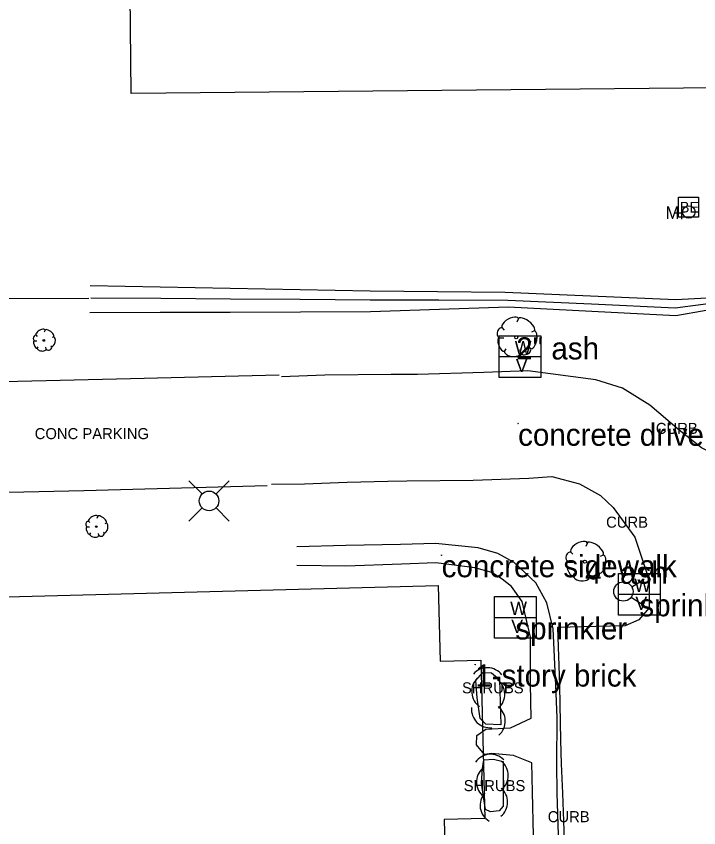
# Model space of a CAD drawing. Extents: x 1802180 to 1804859, y 572524 to 575172.
# Drawn here: x 1803278.7 to 1803432.9, y 574750.8 to 574934.3 of the extents above; entities that cross this region are included whole.
import ezdxf

# ---------------------------------------------------------------- set-up
doc = ezdxf.new("R2010")
doc.units = 0
for name, color, linetype in [('S_BUILDING', 7, 'Continuous'), ('S_CURB_ANNOT', 7, 'Continuous'), ('S_DITCHLINE', 7, 'Continuous'), ('S_ELECTRIC_UTILITIES', 7, 'Continuous'), ('S_MANHOLE', 7, 'Continuous'), ('S_MSC_PT_SYM', 7, 'Continuous'), ('S_PARKING', 7, 'Continuous'), ('S_PARKING_ANNOT', 7, 'Continuous'), ('S_SIDEWALK', 7, 'Continuous'), ('S_STREAM', 7, 'Continuous'), ('S_SURVEY_TEXT_ANNOT', 7, 'Continuous'), ('S_TREE', 7, 'Continuous'), ('S_TREE_ANNOT', 7, 'Continuous'), ('S_UTILITY_POLE', 7, 'Continuous'), ('S_WATER_UTILITIES', 7, 'Continuous'), ('S_WATER_UTILITIES_ANNOT', 7, 'Continuous')]:
    doc.layers.add(name, color=color, linetype=linetype)

msp = doc.modelspace()

# ---------------------------------------------------------------- linework, layer by layer
at = {"layer": 'S_BUILDING'}
for points in [[(1803304.17, 574961.62), (1803436.84, 574962.91), (1803437.28, 574918.07), (1803304.61, 574916.78), (1803304.17, 574961.62)], [(1803186.38, 574730.05), (1803184.53, 574800.55), (1803210.57, 574801.23), (1803210.41, 574807.19), (1803267.74, 574808.69), (1803267.89, 574802.81), (1803374.03, 574805.59), (1803374.48, 574788.48), (1803383.62, 574788.72), (1803384.55, 574752.9), (1803375.35, 574752.66), (1803375.81, 574735.01)]]:
    msp.add_lwpolyline(points, dxfattribs=at)
at = {"layer": 'S_DITCHLINE'}
for points in [[(1803485.39, 574874.75), (1803480.16, 574876.27), (1803462.03, 574877.4), (1803457.78, 574872.83), (1803450.14, 574869.58), (1803434.82, 574870.5), (1803427.71, 574870.12), (1803408.43, 574870.95), (1803389.15, 574871.78), (1803373.89, 574871.95), (1803358.64, 574872.13), (1803342.82, 574872.42), (1803327, 574872.71), (1803311.19, 574873), (1803295.37, 574873.28)], [(1803479.32, 574875.32), (1803464.43, 574874.94), (1803459.71, 574871.25), (1803450.42, 574867.83), (1803435, 574869.25), (1803427.58, 574868.29), (1803408.67, 574869.16), (1803389.76, 574870.03), (1803374.19, 574870.06), (1803358.62, 574870.09), (1803342.85, 574870.2), (1803327.08, 574870.31), (1803311.3, 574870.42), (1803295.53, 574870.53)], [(1803485.66, 574873.78), (1803479.11, 574874.06), (1803465.36, 574872.76), (1803458.52, 574867.76), (1803450.45, 574866.42), (1803434.55, 574867.77), (1803427.69, 574866.53), (1803408.76, 574867.52), (1803389.83, 574868.51), (1803374.28, 574867.97), (1803358.73, 574867.43), (1803342.87, 574867.37), (1803327.01, 574867.31), (1803311.15, 574867.26), (1803295.29, 574867.2)]]:
    msp.add_lwpolyline(points, dxfattribs=at)
at = {"layer": 'S_ELECTRIC_UTILITIES'}
msp.add_lwpolyline([(1803428.33, 574888.83), (1803428.33, 574893.33), (1803432.83, 574893.33), (1803432.83, 574888.83)], close=True, dxfattribs=at)
at = {"layer": 'S_MANHOLE'}
for p, q in [((1803429.07, 574888.39), (1803429.07, 574891.23)), ((1803427.49, 574889.8), (1803429.07, 574889.8))]:
    msp.add_line(p, q, dxfattribs=at)
msp.add_circle((1803430.65, 574890.01), 1.42, dxfattribs=at)
at = {"layer": 'S_MSC_PT_SYM'}
for points in [[(1803392.07, 574842.15), (1803392.07, 574842.2), (1803392.07, 574842.15), (1803392.02, 574842.15), (1803392.07, 574842.15), (1803392.07, 574842.1), (1803392.07, 574842.15), (1803392.12, 574842.15)], [(1803374.8, 574812.43), (1803374.8, 574812.48), (1803374.8, 574812.43), (1803374.75, 574812.43), (1803374.8, 574812.43), (1803374.8, 574812.38), (1803374.8, 574812.43), (1803374.85, 574812.43)], [(1803382.4, 574787.71), (1803382.4, 574787.76), (1803382.4, 574787.71), (1803382.35, 574787.71), (1803382.4, 574787.71), (1803382.4, 574787.66), (1803382.4, 574787.71), (1803382.45, 574787.71)]]:
    msp.add_lwpolyline(points, dxfattribs=at)
at = {"layer": 'S_PARKING'}
for points in [[(1803500.76, 574842.04), (1803493.85, 574835.83), (1803481.9, 574829.92), (1803466.91, 574828.51), (1803462.34, 574828.42), (1803449.1, 574829.09), (1803446.96, 574830.03), (1803433.52, 574836.71), (1803428.46, 574840.7), (1803421.86, 574846.33), (1803415.66, 574850.18), (1803409.67, 574852.09), (1803394.24, 574854.11), (1803384.34, 574853.74), (1803369.31, 574853.26), (1803363.37, 574853.23), (1803348.37, 574853.14), (1803338.64, 574852.72)], [(1803500.76, 574842.04), (1803493.85, 574835.83), (1803481.9, 574829.92), (1803466.91, 574828.51), (1803462.34, 574828.42), (1803449.1, 574829.09), (1803446.96, 574830.03), (1803433.52, 574836.71), (1803428.46, 574840.7), (1803421.86, 574846.33), (1803415.66, 574850.18), (1803409.67, 574852.09), (1803394.24, 574854.11), (1803384.34, 574853.74), (1803369.31, 574853.26), (1803363.37, 574853.23), (1803348.37, 574853.14), (1803338.64, 574852.72)], [(1803218.57, 574850.32), (1803304.52, 574852.39), (1803338.11, 574853.21)], [(1803336.31, 574828.47), (1803343.77, 574828.54), (1803353.45, 574828.95), (1803362.61, 574829.17), (1803366.92, 574829.26), (1803381.95, 574829.39), (1803394.49, 574829.8), (1803399.67, 574830.21), (1803405.93, 574828.55), (1803410.73, 574825.9), (1803413.58, 574823.16), (1803418.42, 574816.47), (1803421.68, 574806.75), (1803421.7, 574800.55), (1803419.35, 574797.8), (1803416.29, 574796.46), (1803409.61, 574796.3), (1803401, 574796.05)], [(1803336.31, 574828.47), (1803343.77, 574828.54), (1803353.45, 574828.95), (1803362.61, 574829.17), (1803366.92, 574829.26), (1803381.95, 574829.39), (1803394.49, 574829.8), (1803399.67, 574830.21), (1803405.93, 574828.55), (1803410.73, 574825.9), (1803413.58, 574823.16), (1803418.42, 574816.47), (1803421.68, 574806.75), (1803421.7, 574800.55), (1803419.35, 574797.8), (1803416.29, 574796.46), (1803409.61, 574796.3), (1803401, 574796.05), (1803401.42, 574783.05), (1803401.54, 574778.66), (1803401.65, 574770.63), (1803401.83, 574765.27), (1803402.07, 574758.62), (1803402.4, 574750.19)], [(1803219.12, 574825.36), (1803293.94, 574827.04), (1803335.4, 574828.2)], [(1803401, 574796.05), (1803401.42, 574783.05), (1803401.54, 574778.66), (1803401.65, 574770.63), (1803401.83, 574765.27), (1803402.07, 574758.62), (1803402.4, 574750.19), (1803402.66, 574741.48), (1803402.67, 574733.22), (1803403.04, 574720.66), (1803403.03, 574716.31), (1803403, 574715.17)]]:
    msp.add_lwpolyline(points, dxfattribs=at)
at = {"layer": 'S_SIDEWALK'}
for points in [[(1803401.18, 574749.16), (1803400.93, 574758.59), (1803400.85, 574765.27), (1803400.92, 574775.65), (1803400.59, 574783.01), (1803400.01, 574795.8), (1803398.55, 574801.66), (1803396.09, 574806.19), (1803391.22, 574810.75), (1803387.53, 574812.79), (1803383.04, 574814.09), (1803373.38, 574815.07), (1803365.5, 574814.84), (1803353.17, 574814.59), (1803342.05, 574814.33)], [(1803395.59, 574749.02), (1803395.34, 574758.81), (1803395.2, 574765.5), (1803391.06, 574767.12), (1803386.07, 574767.55), (1803384.5, 574767.39), (1803382.7, 574769.52), (1803382.72, 574771.65), (1803384.75, 574773.11), (1803390.36, 574773.37), (1803395.06, 574775.54), (1803394.9, 574783.31), (1803394.85, 574793.88), (1803392.97, 574801.94), (1803390.6, 574805.36), (1803388.44, 574806.96), (1803386.1, 574808.53), (1803382.29, 574809.56), (1803373.48, 574810.69), (1803365.72, 574810.41), (1803353.16, 574809.95), (1803342.05, 574810.08)]]:
    msp.add_lwpolyline(points, dxfattribs=at)
at = {"layer": 'S_STREAM'}
msp.add_lwpolyline([(1803227.23, 574905.9), (1803239.77, 574886.65), (1803242.76, 574874.36), (1803242.97, 574873.07), (1803244.13, 574871.72), (1803249.71, 574870.38), (1803295.09, 574870.5)], dxfattribs=at)
at = {"layer": 'S_TREE'}
for p, q in [((1803392.2, 574865.91), (1803391.81, 574865.06)), ((1803285.18, 574863.31), (1803284.97, 574862.84)), ((1803388.4, 574863.9), (1803388.9, 574863.32)), ((1803395.76, 574863.12), (1803395.1, 574862.85)), ((1803283.09, 574862.2), (1803283.37, 574861.87)), ((1803287.15, 574861.77), (1803286.79, 574861.62)), ((1803387.74, 574861.57), (1803388.86, 574861.57)), ((1803282.72, 574860.91), (1803283.34, 574860.91)), ((1803283.37, 574859.16), (1803283.62, 574859.54)), ((1803286.72, 574859.5), (1803286.47, 574859.74)), ((1803285.4, 574859.01), (1803285.35, 574859.44)), ((1803388.9, 574858.39), (1803389.37, 574859.09)), ((1803392.58, 574858.12), (1803392.51, 574858.9)), ((1803394.99, 574859.01), (1803394.52, 574859.44)), ((1803297.07, 574821.21), (1803296.86, 574820.74)), ((1803294.98, 574820.1), (1803295.26, 574819.78)), ((1803299.04, 574819.67), (1803298.68, 574819.52)), ((1803294.61, 574818.81), (1803295.23, 574818.81)), ((1803295.26, 574817.06), (1803295.51, 574817.45)), ((1803297.29, 574816.91), (1803297.24, 574817.34)), ((1803298.61, 574817.4), (1803298.35, 574817.64)), ((1803407.73, 574815.2), (1803407.35, 574814.35)), ((1803403.94, 574813.19), (1803404.44, 574812.61)), ((1803411.3, 574812.41), (1803410.64, 574812.14)), ((1803403.28, 574810.86), (1803404.4, 574810.86)), ((1803404.44, 574807.69), (1803404.91, 574808.38)), ((1803408.12, 574807.42), (1803408.04, 574808.19)), ((1803410.52, 574808.31), (1803410.06, 574808.73))]:
    msp.add_line(p, q, dxfattribs=at)
for points in [[(1803387.85, 574784.28), (1803388.18, 574774.09), (1803384.78, 574774.18), (1803383.48, 574775.46), (1803382.85, 574780.18), (1803382.52, 574784.12), (1803384.14, 574785.86), (1803386.08, 574785.8), (1803387.85, 574784.28)], [(1803388.73, 574765.8), (1803388.68, 574755.65), (1803387.77, 574754.62), (1803385.87, 574754.41), (1803384.71, 574754.91), (1803384.25, 574757.8), (1803383.79, 574760.92), (1803384.02, 574764.18), (1803384.31, 574766.16), (1803386.55, 574766.34), (1803388.73, 574765.8)]]:
    msp.add_lwpolyline(points, dxfattribs=at)
for centre, radius in [((1803391.64, 574861.67), 0.341), ((1803284.88, 574860.96), 0.188), ((1803296.76, 574818.87), 0.188), ((1803407.18, 574810.96), 0.341)]:
    msp.add_circle(centre, radius, dxfattribs=at)
for centre, radius, start, end in [((1803385.11, 574782.83), 4.15, 37.4841, 139.0811), ((1803385.73, 574781.61), 4.15, 133.9302, 235.5271), ((1803384.92, 574780.97), 4.15, 311.0212, 52.6181), ((1803385.69, 574777.55), 4.15, 174.4937, 276.0906), ((1803385.03, 574774.89), 4.15, 311.0212, 52.6181), ((1803385.84, 574763.3), 4.12, 43.826, 145.4229), ((1803386.78, 574761.13), 4.12, 125.3233, 226.9202), ((1803385.71, 574762.63), 4.12, 308.9188, 50.5158), ((1803387.6, 574755.87), 4.12, 138.1892, 239.7861), ((1803385.59, 574756.6), 4.12, 308.9188, 50.5158)]:
    msp.add_arc(centre, radius, start, end, dxfattribs=at)
for centre, major_axis, ratio, start_param, end_param in [((1803390.3, 574864.87), (1.86, 1.08), 0.471018, 0, 3.141593), ((1803393.96, 574864.55), (-1.81, 1.36), 0.405113, 3.141593, 6.283186), ((1803284.14, 574862.73), (1.02, 0.6), 0.471018, 0, 3.141593), ((1803286.15, 574862.55), (-1, 0.75), 0.405113, 3.141593, 6.283186), ((1803388.07, 574862.75), (0.31, 1.03), 0.646762, 0, 3.141593), ((1803395.31, 574861.14), (0.46, 2.04), 0.482994, 3.141593, 6.283185), ((1803282.91, 574861.56), (0.168, 0.567), 0.646762, 0, 3.141593), ((1803286.9, 574860.67), (0.25, 1.13), 0.482994, 3.141593, 6.283185), ((1803388.37, 574860.1), (-0.61, 1.6), 0.420543, 6.283185, 9.424777), ((1803283.07, 574860.1), (-0.337, 0.88), 0.420543, 6.283185, 9.424777), ((1803286.06, 574859.28), (0.602, 0.255), 0.711534, 3.141592, 6.283185), ((1803284.43, 574859.12), (-1.01, 0.11), 0.529943, 0, 3.141593), ((1803390.83, 574858.32), (-1.83, 0.19), 0.529943, 0, 3.141593), ((1803393.79, 574858.62), (1.09, 0.46), 0.711534, 3.141592, 6.283185), ((1803296.03, 574820.63), (1.02, 0.6), 0.471018, 0, 3.141593), ((1803298.04, 574820.46), (-1, 0.75), 0.405113, 3.141593, 6.283186), ((1803294.79, 574819.47), (0.168, 0.567), 0.646762, 0, 3.141593), ((1803298.79, 574818.57), (0.25, 1.13), 0.482994, 3.141593, 6.283185), ((1803294.96, 574818), (-0.337, 0.88), 0.420543, 6.283185, 9.424777), ((1803297.95, 574817.18), (0.602, 0.255), 0.711534, 3.141592, 6.283185), ((1803296.32, 574817.02), (-1.01, 0.11), 0.529943, 0, 3.141593), ((1803405.84, 574814.16), (1.86, 1.08), 0.471018, 0, 3.141593), ((1803409.5, 574813.84), (-1.81, 1.36), 0.405113, 3.141593, 6.283186), ((1803403.61, 574812.05), (0.31, 1.03), 0.646762, 0, 3.141593), ((1803410.85, 574810.43), (0.46, 2.04), 0.482994, 3.141593, 6.283185), ((1803403.91, 574809.4), (-0.61, 1.6), 0.420543, 6.283185, 9.424777), ((1803409.33, 574807.91), (1.09, 0.46), 0.711534, 3.141592, 6.283185), ((1803406.37, 574807.62), (-1.83, 0.19), 0.529943, 0, 3.141593)]:
    msp.add_ellipse(centre, major_axis=major_axis, ratio=ratio, start_param=start_param, end_param=end_param, dxfattribs=at)
at = {"layer": 'S_UTILITY_POLE'}
for p, q in [((1803320.65, 574826.27), (1803317.66, 574829.25)), ((1803323.82, 574826.27), (1803326.81, 574829.25)), ((1803320.65, 574823.09), (1803317.66, 574820.11)), ((1803323.82, 574823.09), (1803326.81, 574820.11))]:
    msp.add_line(p, q, dxfattribs=at)
msp.add_circle((1803322.24, 574824.69), 2.21, dxfattribs=at)
at = {"layer": 'S_WATER_UTILITIES'}
for p, q in [((1803387.77, 574862.02), (1803397.18, 574862.02)), ((1803387.77, 574852.6), (1803387.77, 574862.02)), ((1803397.18, 574862.02), (1803397.18, 574852.6)), ((1803387.77, 574857.33), (1803397.18, 574857.33)), ((1803397.18, 574852.6), (1803387.77, 574852.6)), ((1803414.78, 574808.28), (1803424.2, 574808.28)), ((1803414.78, 574798.86), (1803414.78, 574808.28)), ((1803424.2, 574808.28), (1803424.2, 574798.86)), ((1803417.76, 574805.26), (1803420.59, 574806.99)), ((1803386.74, 574803.05), (1803396.15, 574803.05)), ((1803386.74, 574793.63), (1803386.74, 574803.05)), ((1803396.15, 574803.05), (1803396.15, 574793.63)), ((1803414.78, 574803.59), (1803424.2, 574803.59)), ((1803417.64, 574802.95), (1803420.55, 574801.02)), ((1803386.74, 574798.36), (1803396.15, 574798.36)), ((1803424.2, 574798.86), (1803414.78, 574798.86)), ((1803396.15, 574793.63), (1803386.74, 574793.63))]:
    msp.add_line(p, q, dxfattribs=at)
msp.add_circle((1803415.86, 574804.2), 2.18, dxfattribs=at)

# ---------------------------------------------------------------- texts
at = {"layer": 'S_CURB_ANNOT'}
for p in [(1803423.2, 574839.83), (1803411.96, 574818.63), (1803398.77, 574752.05)]:
    msp.add_text('CURB', height=2.5, dxfattribs=at).set_placement(p)
at = {"layer": 'S_ELECTRIC_UTILITIES'}
msp.add_text('BE', height=2.4, rotation=360, dxfattribs=at).set_placement((1803428.64, 574889.88))
at = {"layer": 'S_MANHOLE'}
msp.add_text('M', height=2.82, dxfattribs=at).set_placement((1803425.4, 574888.43))
at = {"layer": 'S_PARKING_ANNOT'}
msp.add_text('CONC PARKING', height=2.5, dxfattribs=at).set_placement((1803282.84, 574838.65))
at = {"layer": 'S_SURVEY_TEXT_ANNOT'}
for s, p in [('concrete drive ', (1803392.07, 574837.15)), ('concrete sidewalk ', (1803374.8, 574807.43)), ('1-story brick ', (1803382.4, 574782.71))]:
    msp.add_text(s, height=5, dxfattribs=at).set_placement(p)
at = {"layer": 'S_TREE_ANNOT'}
for s, height, p in [('2" ash ', 5, (1803391.64, 574856.67)), ('4" ash ', 5, (1803407.18, 574805.96)), ('SHRUBS', 2.5, (1803379.4, 574781.18)), ('SHRUBS', 2.5, (1803379.78, 574759.07))]:
    msp.add_text(s, height=height, dxfattribs=at).set_placement(p)
at = {"layer": 'S_WATER_UTILITIES'}
for s, p in [('W', (1803391.32, 574857.86)), ('V', (1803391.55, 574853.8)), ('W', (1803418.33, 574804.12)), ('V', (1803418.57, 574800.06)), ('W', (1803390.29, 574798.89)), ('V', (1803390.52, 574794.83))]:
    msp.add_text(s, height=3, rotation=360, dxfattribs=at).set_placement(p)
at = {"layer": 'S_WATER_UTILITIES_ANNOT'}
for p in [(1803419.49, 574798.59), (1803391.45, 574793.36)]:
    msp.add_text('sprinkler ', height=5, dxfattribs=at).set_placement(p)

doc.saveas('drawing.dxf')
